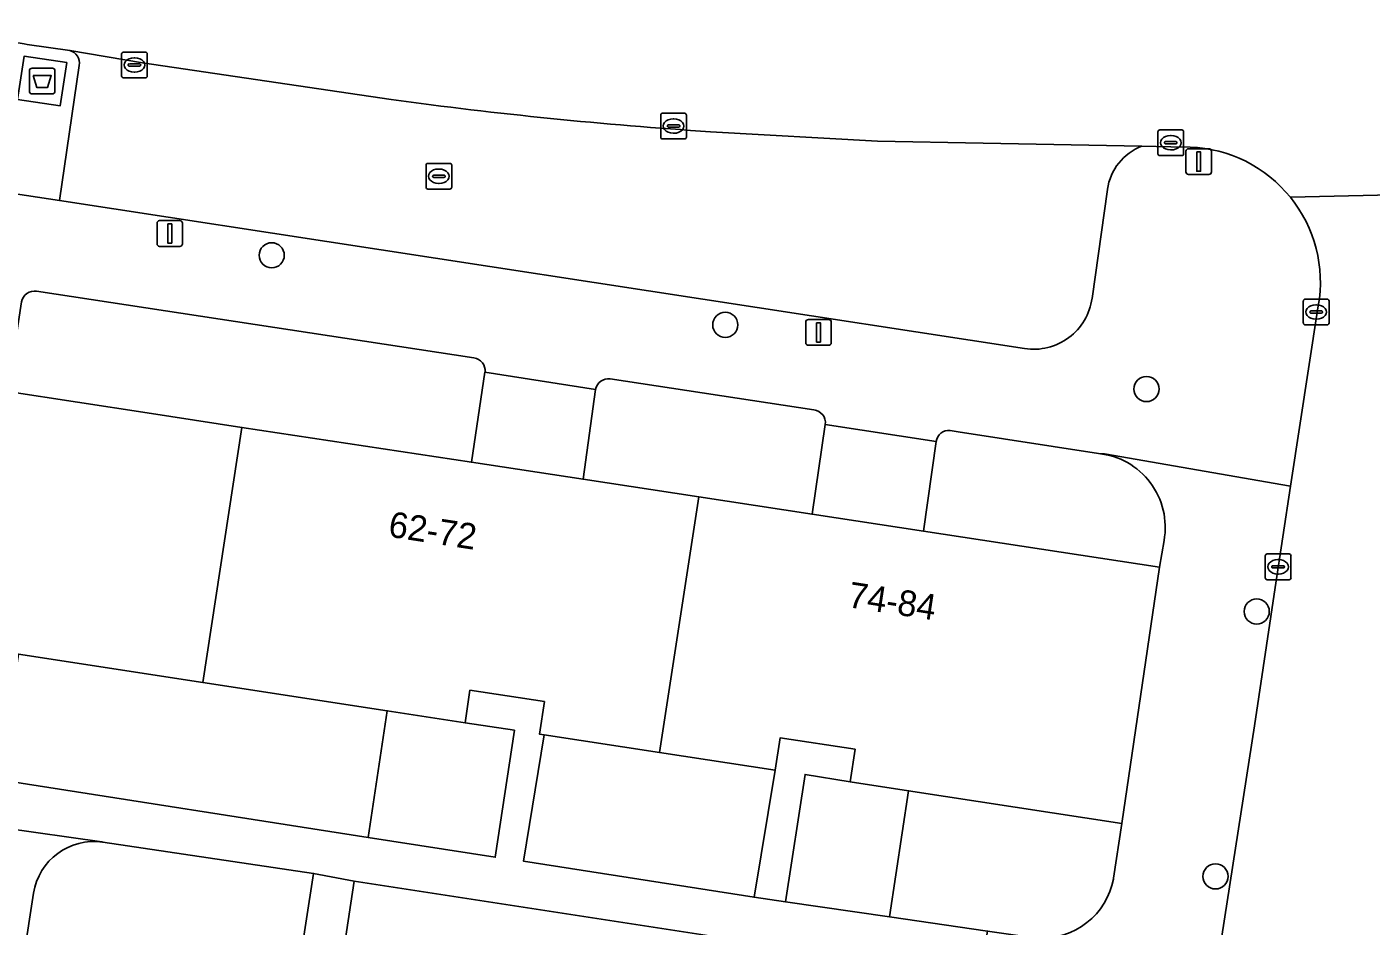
# Model space of a CAD drawing. Extents: x 161084 to 161928, y 385354 to 386522.
# Drawn here: x 161701.9 to 161754.2, y 385605.1 to 385640 of the extents above; entities that cross this region are included whole.
import ezdxf

# ---------------------------------------------------------------- set-up
doc = ezdxf.new("R2010")
doc.units = 0
for name, color, linetype in [('IMGEO_Afval_apart_plaats', 7, 'Continuous'), ('IMGEO_Boom', 7, 'Continuous'), ('IMGEO_Groenvoorziening', 7, 'Continuous'), ('IMGEO_Kolk', 7, 'Continuous'), ('IMGEO_Lichtmast', 7, 'Continuous'), ('IMGEO_Pand', 7, 'Continuous'), ('IMGEO_Pand_nummerreeks', 7, 'Continuous'), ('IMGEO_Parkeervlak_open', 7, 'Continuous'), ('IMGEO_Rijbaan_lokaal_open', 7, 'Continuous'), ('IMGEO_Rioolput', 7, 'Continuous'), ('IMGEO_Voetpad_gesloten', 7, 'Continuous'), ('IMGEO_Voetpad_open', 7, 'Continuous')]:
    doc.layers.add(name, color=color, linetype=linetype)

msp = doc.modelspace()

# ---------------------------------------------------------------- linework, layer by layer
at = {"layer": 'IMGEO_Afval_apart_plaats'}
for p, q in [((161702.13, 385638.394), (161702.92, 385638.394)), ((161702.92, 385638.394), (161702.13, 385638.394)), ((161702.03, 385637.494), (161702.03, 385638.294)), ((161702.03, 385638.294), (161702.03, 385637.494)), ((161703.02, 385638.294), (161703.02, 385637.494)), ((161703.02, 385637.494), (161703.02, 385638.294)), ((161702.92, 385637.394), (161702.13, 385637.394)), ((161702.13, 385637.394), (161702.92, 385637.394))]:
    msp.add_line(p, q, dxfattribs=at)
msp.add_lwpolyline([(161702.173, 385638.108), (161702.877, 385638.108), (161702.728, 385637.638), (161702.322, 385637.638), (161702.173, 385638.108)], dxfattribs=at)
for centre, start, end in [((161702.13, 385638.294), 90, 180), ((161702.13, 385638.294), 90, 180), ((161702.92, 385638.294), 0, 90), ((161702.92, 385638.294), 360, 90), ((161702.13, 385637.494), 180, 270), ((161702.13, 385637.494), 180, 270), ((161702.92, 385637.494), 270, 0), ((161702.92, 385637.494), 270, 0)]:
    msp.add_arc(centre, 0.1, start, end, dxfattribs=at)
at = {"layer": 'IMGEO_Boom'}
for centre in [(161711.448, 385631.125), (161729.079, 385628.421), (161745.453, 385625.929), (161749.736, 385617.286), (161748.133, 385606.997)]:
    msp.add_circle(centre, 0.489, dxfattribs=at)
at = {"layer": 'IMGEO_Groenvoorziening'}
for points in [[(161719.303, 385627.14), (161702.307, 385629.729)], [(161701.725, 385629.314), (161701.191, 385625.827), (161706.607, 385625.002), (161710.291, 385624.441), (161719.211, 385623.083), (161719.738, 385626.581)], [(161732.527, 385625.122), (161724.601, 385626.328)], [(161724.038, 385625.907), (161723.549, 385622.423), (161728.049, 385621.738), (161732.452, 385621.067), (161732.966, 385624.551)], [(161743.587, 385623.423), (161738.133, 385624.272), (161737.819, 385624.321)], [(161737.273, 385623.887), (161736.785, 385620.408), (161745.953, 385619.012), (161746.133, 385620.045)], [(161702.191, 385606.341), (161697.119, 385573.437), (161707.611, 385571.788), (161713.072, 385607.113), (161704.883, 385608.326)], [(161736.552, 385603.449), (161714.658, 385606.809), (161709.299, 385571.47), (161731.363, 385568.084)]]:
    msp.add_lwpolyline(points, dxfattribs=at)
for points in [[(161715.193, 385608.513), (161715.938, 385613.431), (161708.772, 385614.53), (161701.606, 385615.629), (161700.866, 385610.749), (161701.288, 385610.683)], [(161720.134, 385607.742), (161720.881, 385612.673), (161718.961, 385612.968), (161715.938, 385613.431), (161715.193, 385608.513)], [(161730.197, 385606.186), (161731.021, 385611.119), (161726.527, 385611.808), (161722.032, 385612.497), (161721.233, 385607.593)], [(161735.459, 385605.43), (161736.201, 385610.325), (161733.93, 385610.673), (161732.178, 385610.956), (161731.425, 385606.015)], [(161743.925, 385606.175), (161744.027, 385606.407), (161744.108, 385606.647), (161744.167, 385606.893), (161744.173, 385606.922), (161744.491, 385609.053), (161736.201, 385610.325), (161735.459, 385605.43), (161739.275, 385604.876), (161740.99, 385604.627), (161741.242, 385604.603), (161741.495, 385604.601), (161741.748, 385604.622), (161741.997, 385604.665), (161742.242, 385604.731), (161742.479, 385604.818), (161742.708, 385604.926), (161742.927, 385605.054), (161743.133, 385605.201), (161743.325, 385605.366), (161743.502, 385605.547), (161743.662, 385605.743), (161743.803, 385605.953)]]:
    msp.add_lwpolyline(points, close=True, dxfattribs=at)
for centre, radius, start, end in [((161702.221, 385629.234), 0.502, 80.1099, 170.8723), ((161719.236, 385626.639), 0.506, 353.4375, 82.3408), ((161724.54, 385625.822), 0.509, 83.1576, 170.4192), ((161732.459, 385624.615), 0.511, 352.7869, 82.3211), ((161737.777, 385623.813), 0.509, 85.2851, 171.6753), ((161743.305, 385620.562), 2.875, 349.6426, 84.368), ((161704.535, 385605.98), 2.372, 81.5728, 171.2351)]:
    msp.add_arc(centre, radius, start, end, dxfattribs=at)
at = {"layer": 'IMGEO_Kolk'}
for p, q in [((161705.611, 385638.091), (161705.611, 385638.943)), ((161705.686, 385639.017), (161706.538, 385639.017)), ((161706.612, 385638.943), (161706.612, 385638.091)), ((161705.87, 385638.511), (161705.87, 385638.523)), ((161706.308, 385638.474), (161705.91, 385638.474)), ((161705.913, 385638.56), (161706.311, 385638.56)), ((161706.099, 385638.797), (161706.124, 385638.797)), ((161706.354, 385638.523), (161706.354, 385638.511)), ((161706.538, 385638.017), (161705.686, 385638.017)), ((161706.122, 385638.237), (161706.097, 385638.237)), ((161726.569, 385635.719), (161726.569, 385636.571)), ((161726.644, 385636.645), (161727.496, 385636.645)), ((161727.057, 385636.425), (161727.082, 385636.425)), ((161727.57, 385636.571), (161727.57, 385635.719)), ((161726.828, 385636.139), (161726.828, 385636.151)), ((161727.266, 385636.102), (161726.868, 385636.102)), ((161726.871, 385636.188), (161727.269, 385636.188)), ((161727.08, 385635.865), (161727.055, 385635.865)), ((161727.312, 385636.151), (161727.312, 385636.139)), ((161745.894, 385635.071), (161745.894, 385635.923)), ((161745.969, 385635.997), (161746.821, 385635.997)), ((161746.382, 385635.777), (161746.407, 385635.777)), ((161746.895, 385635.923), (161746.895, 385635.071)), ((161727.496, 385635.645), (161726.644, 385635.645)), ((161746.153, 385635.491), (161746.153, 385635.503)), ((161746.591, 385635.454), (161746.193, 385635.454)), ((161746.196, 385635.54), (161746.594, 385635.54)), ((161746.405, 385635.217), (161746.38, 385635.217)), ((161746.637, 385635.503), (161746.637, 385635.491)), ((161746.821, 385634.997), (161745.969, 385634.997)), ((161751.548, 385628.496), (161751.548, 385629.348)), ((161751.623, 385629.422), (161752.475, 385629.422)), ((161751.807, 385628.916), (161751.807, 385628.928)), ((161751.85, 385628.965), (161752.248, 385628.965)), ((161752.036, 385629.202), (161752.061, 385629.202)), ((161752.291, 385628.928), (161752.291, 385628.916)), ((161752.549, 385629.348), (161752.549, 385628.496)), ((161752.475, 385628.422), (161751.623, 385628.422)), ((161752.245, 385628.879), (161751.847, 385628.879)), ((161752.059, 385628.642), (161752.034, 385628.642)), ((161750.143, 385619.523), (161750.995, 385619.523)), ((161750.068, 385618.597), (161750.068, 385619.449)), ((161750.327, 385619.017), (161750.327, 385619.029)), ((161750.37, 385619.066), (161750.768, 385619.066)), ((161750.556, 385619.303), (161750.581, 385619.303)), ((161750.811, 385619.029), (161750.811, 385619.017)), ((161751.069, 385619.449), (161751.069, 385618.597)), ((161750.995, 385618.523), (161750.143, 385618.523)), ((161750.765, 385618.98), (161750.367, 385618.98)), ((161750.579, 385618.743), (161750.554, 385618.743))]:
    msp.add_line(p, q, dxfattribs=at)
for points in [[(161705.611, 385638.091), (161705.611, 385638.943)], [(161705.686, 385639.017), (161706.538, 385639.017)], [(161706.612, 385638.943), (161706.612, 385638.091)], [(161706.538, 385638.017), (161705.686, 385638.017)], [(161726.569, 385635.719), (161726.569, 385636.571)], [(161726.644, 385636.645), (161727.496, 385636.645)], [(161727.57, 385636.571), (161727.57, 385635.719)], [(161745.894, 385635.071), (161745.894, 385635.923)], [(161745.969, 385635.997), (161746.821, 385635.997)], [(161746.895, 385635.923), (161746.895, 385635.071)], [(161727.496, 385635.645), (161726.644, 385635.645)], [(161746.821, 385634.997), (161745.969, 385634.997)], [(161751.548, 385628.496), (161751.548, 385629.348)], [(161751.623, 385629.422), (161752.475, 385629.422)], [(161752.549, 385629.348), (161752.549, 385628.496)], [(161752.475, 385628.422), (161751.623, 385628.422)], [(161750.143, 385619.523), (161750.995, 385619.523)], [(161750.068, 385618.597), (161750.068, 385619.449)], [(161751.069, 385619.449), (161751.069, 385618.597)], [(161750.995, 385618.523), (161750.143, 385618.523)]]:
    msp.add_lwpolyline(points, dxfattribs=at)
for centre, radius, start, end in [((161705.688, 385638.941), 0.0765, 91.552, 178.448), ((161705.688, 385638.941), 0.0765, 91.552, 178.448), ((161706.536, 385638.941), 0.0765, 1.552, 88.448), ((161706.536, 385638.941), 0.0765, 1.552, 88.448), ((161705.91, 385638.52), 0.0403, 85.8775, 175.7526), ((161705.907, 385638.51), 0.0366, 178.938, 274.7102), ((161706.311, 385638.517), 0.043, 264.8664, 352.4533), ((161706.315, 385638.522), 0.0386, 1.7309, 96.639), ((161705.688, 385638.093), 0.0765, 181.552, 268.448), ((161705.688, 385638.093), 0.0765, 181.552, 268.448), ((161706.536, 385638.093), 0.0765, 271.552, 358.448), ((161706.536, 385638.093), 0.0765, 271.552, 358.448), ((161726.646, 385636.569), 0.0765, 91.552, 178.448), ((161726.646, 385636.569), 0.0765, 91.552, 178.448), ((161727.494, 385636.569), 0.0765, 1.552, 88.448), ((161727.494, 385636.569), 0.0765, 1.552, 88.448), ((161726.646, 385635.721), 0.0765, 181.552, 268.448), ((161726.646, 385635.721), 0.0765, 181.552, 268.448), ((161726.868, 385636.148), 0.0403, 85.8775, 175.7526), ((161726.865, 385636.138), 0.0366, 178.938, 274.7102), ((161727.269, 385636.145), 0.043, 264.8664, 352.4533), ((161727.273, 385636.15), 0.0386, 1.7309, 96.639), ((161727.494, 385635.721), 0.0765, 271.552, 358.448), ((161727.494, 385635.721), 0.0765, 271.552, 358.448), ((161745.971, 385635.921), 0.0765, 91.552, 178.448), ((161745.971, 385635.921), 0.0765, 91.552, 178.448), ((161746.819, 385635.921), 0.0765, 1.552, 88.448), ((161746.819, 385635.921), 0.0765, 1.552, 88.448), ((161746.193, 385635.5), 0.0403, 85.8775, 175.7526), ((161746.19, 385635.49), 0.0366, 178.938, 274.7102), ((161746.594, 385635.497), 0.043, 264.8664, 352.4533), ((161746.598, 385635.502), 0.0386, 1.7309, 96.639), ((161745.971, 385635.073), 0.0765, 181.552, 268.448), ((161745.971, 385635.073), 0.0765, 181.552, 268.448), ((161746.819, 385635.073), 0.0765, 271.552, 358.448), ((161746.819, 385635.073), 0.0765, 271.552, 358.448), ((161751.625, 385629.346), 0.0765, 91.552, 178.448), ((161751.625, 385629.346), 0.0765, 91.552, 178.448), ((161751.847, 385628.925), 0.0403, 85.8775, 175.7526), ((161752.252, 385628.927), 0.0386, 1.7309, 96.639), ((161752.473, 385629.346), 0.0765, 1.552, 88.448), ((161752.473, 385629.346), 0.0765, 1.552, 88.448), ((161751.625, 385628.498), 0.0765, 181.552, 268.448), ((161751.625, 385628.498), 0.0765, 181.552, 268.448), ((161751.844, 385628.915), 0.0366, 178.938, 274.7102), ((161752.248, 385628.922), 0.043, 264.8664, 352.4533), ((161752.473, 385628.498), 0.0765, 271.552, 358.448), ((161752.473, 385628.498), 0.0765, 271.552, 358.448), ((161750.145, 385619.447), 0.0765, 91.552, 178.448), ((161750.145, 385619.447), 0.0765, 91.552, 178.448), ((161750.993, 385619.447), 0.0765, 1.552, 88.448), ((161750.993, 385619.447), 0.0765, 1.552, 88.448), ((161750.367, 385619.026), 0.0403, 85.8775, 175.7526), ((161750.364, 385619.016), 0.0366, 178.938, 274.7102), ((161750.768, 385619.023), 0.043, 264.8664, 352.4533), ((161750.772, 385619.028), 0.0386, 1.7309, 96.639), ((161750.145, 385618.599), 0.0765, 181.552, 268.448), ((161750.145, 385618.599), 0.0765, 181.552, 268.448), ((161750.993, 385618.599), 0.0765, 271.552, 358.448), ((161750.993, 385618.599), 0.0765, 271.552, 358.448)]:
    msp.add_arc(centre, radius, start, end, dxfattribs=at)
for centre, major_axis, ratio, start_param, end_param in [((161706.098, 385638.517), (-0.387, 0.002), 0.722429, 4.712389, 7.853982), ((161706.123, 385638.517), (-0.39, 0.002), 0.717154, 1.570796, 4.712389), ((161727.056, 385636.145), (-0.387, 0.002), 0.722429, 4.712389, 7.853982), ((161727.081, 385636.145), (-0.39, 0.002), 0.717154, 1.570796, 4.712389), ((161746.381, 385635.497), (-0.387, 0.002), 0.722429, 4.712389, 7.853982), ((161746.406, 385635.497), (-0.39, 0.002), 0.717154, 1.570796, 4.712389), ((161752.035, 385628.922), (-0.387, 0.002), 0.722429, 4.712389, 7.853982), ((161752.06, 385628.922), (-0.39, 0.002), 0.717154, 1.570796, 4.712389), ((161750.555, 385619.023), (-0.387, 0.002), 0.722429, 4.712389, 7.853982), ((161750.58, 385619.023), (-0.39, 0.002), 0.717154, 1.570796, 4.712389)]:
    msp.add_ellipse(centre, major_axis=major_axis, ratio=ratio, start_param=start_param, end_param=end_param, dxfattribs=at)
at = {"layer": 'IMGEO_Lichtmast'}
for p, q in [((161747.086, 385635.263), (161747.876, 385635.263)), ((161747.876, 385635.263), (161747.086, 385635.263)), ((161746.986, 385634.363), (161746.986, 385635.163)), ((161746.986, 385635.163), (161746.986, 385634.363)), ((161747.976, 385635.163), (161747.976, 385634.363)), ((161747.976, 385634.363), (161747.976, 385635.163)), ((161747.876, 385634.263), (161747.086, 385634.263)), ((161747.086, 385634.263), (161747.876, 385634.263)), ((161706.989, 385631.571), (161706.989, 385632.371)), ((161706.989, 385632.371), (161706.989, 385631.571)), ((161707.089, 385632.471), (161707.879, 385632.471)), ((161707.879, 385632.471), (161707.089, 385632.471)), ((161707.979, 385632.371), (161707.979, 385631.571)), ((161707.979, 385631.571), (161707.979, 385632.371)), ((161707.879, 385631.471), (161707.089, 385631.471)), ((161707.089, 385631.471), (161707.879, 385631.471)), ((161732.207, 385627.729), (161732.207, 385628.529)), ((161732.207, 385628.529), (161732.207, 385627.729)), ((161732.307, 385628.629), (161733.097, 385628.629)), ((161733.097, 385628.629), (161732.307, 385628.629)), ((161733.197, 385628.529), (161733.197, 385627.729)), ((161733.197, 385627.729), (161733.197, 385628.529)), ((161733.097, 385627.629), (161732.307, 385627.629)), ((161732.307, 385627.629), (161733.097, 385627.629))]:
    msp.add_line(p, q, dxfattribs=at)
for points in [[(161747.406, 385635.138), (161747.556, 385635.138), (161747.556, 385634.388), (161747.406, 385634.388), (161747.406, 385635.138)], [(161707.409, 385632.346), (161707.559, 385632.346), (161707.559, 385631.596), (161707.409, 385631.596), (161707.409, 385632.346)], [(161732.627, 385628.504), (161732.777, 385628.504), (161732.777, 385627.754), (161732.627, 385627.754), (161732.627, 385628.504)]]:
    msp.add_lwpolyline(points, dxfattribs=at)
for centre, start, end in [((161747.086, 385635.163), 90, 180), ((161747.086, 385635.163), 90, 180), ((161747.876, 385635.163), 0, 90), ((161747.876, 385635.163), 360, 90), ((161747.086, 385634.363), 180, 270), ((161747.086, 385634.363), 180, 270), ((161747.876, 385634.363), 270, 0), ((161747.876, 385634.363), 270, 0), ((161707.089, 385632.371), 90, 180), ((161707.089, 385632.371), 90, 180), ((161707.879, 385632.371), 0, 90), ((161707.879, 385632.371), 360, 90), ((161707.089, 385631.571), 180, 270), ((161707.089, 385631.571), 180, 270), ((161707.879, 385631.571), 270, 0), ((161707.879, 385631.571), 270, 0), ((161732.307, 385628.529), 90, 180), ((161732.307, 385628.529), 90, 180), ((161733.097, 385628.529), 0, 90), ((161733.097, 385628.529), 360, 90), ((161732.307, 385627.729), 180, 270), ((161732.307, 385627.729), 180, 270), ((161733.097, 385627.729), 270, 0), ((161733.097, 385627.729), 270, 0)]:
    msp.add_arc(centre, 0.1, start, end, dxfattribs=at)
at = {"layer": 'IMGEO_Pand'}
for points in [[(161706.607, 385625.002), (161701.191, 385625.827), (161696.834, 385626.49), (161692.212, 385627.194), (161691.504, 385622.944), (161691.308, 385621.667), (161690.64, 385617.31), (161695.295, 385616.596), (161695.489, 385617.86), (161698.408, 385617.412), (161698.214, 385616.149), (161701.606, 385615.629), (161708.772, 385614.53), (161710.291, 385624.441)], [(161723.549, 385622.423), (161719.211, 385623.083), (161710.291, 385624.441), (161708.772, 385614.53), (161715.938, 385613.431), (161718.961, 385612.968), (161719.155, 385614.231), (161722.045, 385613.788), (161721.851, 385612.525), (161722.032, 385612.497), (161726.527, 385611.808), (161728.049, 385621.738)], [(161728.049, 385621.738), (161726.527, 385611.808), (161731.021, 385611.119), (161731.215, 385612.382), (161734.124, 385611.936), (161733.93, 385610.673), (161736.201, 385610.325), (161744.491, 385609.053), (161745.953, 385619.012), (161736.785, 385620.408), (161732.452, 385621.067)]]:
    msp.add_lwpolyline(points, close=True, dxfattribs=at)
at = {"layer": 'IMGEO_Parkeervlak_open'}
for points in [[(161716.095, 385637.177), (161706.425, 385638.596), (161703.594, 385639.074)], [(161703.966, 385638.503), (161703.201, 385633.251), (161740.712, 385627.499)], [(161745.271, 385635.362), (161739.101, 385635.482), (161734.991, 385635.562), (161728.498, 385635.926)], [(161743.338, 385629.452), (161743.934, 385633.686)]]:
    msp.add_lwpolyline(points, dxfattribs=at)
for centre, radius, start, end in [((161703.489, 385638.599), 0.487, 348.6292, 77.5384), ((161739.697, 385809.071), 173.507, 262.18177, 266.29917), ((161746.026, 385633.389), 2.113, 110.9325, 171.9065), ((161741.06, 385629.773), 2.3, 261.2912, 351.9864)]:
    msp.add_arc(centre, radius, start, end, dxfattribs=at)
at = {"layer": 'IMGEO_Rijbaan_lokaal_open'}
for points in [[(161684.542, 385642.126), (161687.896, 385641.585), (161701.831, 385639.333), (161701.945, 385639.315), (161703.594, 385639.074), (161706.425, 385638.596), (161716.095, 385637.177)], [(161728.498, 385635.926), (161734.991, 385635.562), (161739.101, 385635.482), (161745.271, 385635.362), (161746.396, 385635.341), (161747.153, 385635.326)], [(161761.205, 385633.614), (161751.044, 385633.38)], [(161751.044, 385633.38), (161761.205, 385633.614)], [(161752.13, 385629.167), (161751.053, 385622.152), (161750.449, 385618.218), (161749.647, 385612.852), (161748.381, 385604.68)]]:
    msp.add_lwpolyline(points, dxfattribs=at)
for centre, radius, start, end in [((161739.697, 385809.071), 173.507, 262.18177, 266.29917), ((161746.962, 385630.081), 5.248, 38.9421, 87.9161), ((161746.96, 385630.081), 5.25, 349.9775, 38.9319)]:
    msp.add_arc(centre, radius, start, end, dxfattribs=at)
at = {"layer": 'IMGEO_Rioolput'}
for p, q in [((161717.52, 385634.695), (161718.372, 385634.695)), ((161717.445, 385633.769), (161717.445, 385634.621)), ((161717.704, 385634.189), (161717.704, 385634.201)), ((161718.142, 385634.152), (161717.744, 385634.152)), ((161717.747, 385634.238), (161718.145, 385634.238)), ((161717.933, 385634.475), (161717.958, 385634.475)), ((161718.188, 385634.201), (161718.188, 385634.189)), ((161718.446, 385634.621), (161718.446, 385633.769)), ((161718.372, 385633.695), (161717.52, 385633.695)), ((161717.956, 385633.915), (161717.931, 385633.915))]:
    msp.add_line(p, q, dxfattribs=at)
for points in [[(161717.52, 385634.695), (161718.372, 385634.695)], [(161717.445, 385633.769), (161717.445, 385634.621)], [(161718.446, 385634.621), (161718.446, 385633.769)], [(161718.372, 385633.695), (161717.52, 385633.695)]]:
    msp.add_lwpolyline(points, dxfattribs=at)
for centre, radius, start, end in [((161717.522, 385634.619), 0.0765, 91.552, 178.448), ((161717.522, 385634.619), 0.0765, 91.552, 178.448), ((161718.37, 385634.619), 0.0765, 1.552, 88.448), ((161718.37, 385634.619), 0.0765, 1.552, 88.448), ((161717.744, 385634.198), 0.0403, 85.8775, 175.7526), ((161717.741, 385634.188), 0.0366, 178.938, 274.7102), ((161718.145, 385634.195), 0.043, 264.8664, 352.4533), ((161718.149, 385634.2), 0.0386, 1.7309, 96.639), ((161717.522, 385633.771), 0.0765, 181.552, 268.448), ((161717.522, 385633.771), 0.0765, 181.552, 268.448), ((161718.37, 385633.771), 0.0765, 271.552, 358.448), ((161718.37, 385633.771), 0.0765, 271.552, 358.448)]:
    msp.add_arc(centre, radius, start, end, dxfattribs=at)
for centre, major_axis, ratio, start_param, end_param in [((161717.932, 385634.195), (-0.387, 0.002), 0.722429, 4.712389, 7.853982), ((161717.957, 385634.195), (-0.39, 0.002), 0.717154, 1.570796, 4.712389)]:
    msp.add_ellipse(centre, major_axis=major_axis, ratio=ratio, start_param=start_param, end_param=end_param, dxfattribs=at)
at = {"layer": 'IMGEO_Voetpad_gesloten'}
msp.add_lwpolyline([(161703.481, 385638.609), (161701.821, 385638.859), (161701.568, 385637.18), (161703.228, 385636.93)], close=True, dxfattribs=at)
at = {"layer": 'IMGEO_Voetpad_open'}
for points in [[(161701.328, 385638.883), (161700.616, 385633.647), (161703.201, 385633.251), (161703.966, 385638.503)], [(161703.594, 385639.074), (161701.945, 385639.315), (161701.831, 385639.333)], [(161747.153, 385635.326), (161746.396, 385635.341), (161745.271, 385635.362)], [(161703.201, 385633.251), (161700.616, 385633.647), (161691.142, 385635.1)], [(161743.934, 385633.686), (161743.338, 385629.452)], [(161740.712, 385627.499), (161703.201, 385633.251)], [(161702.307, 385629.729), (161719.303, 385627.14)], [(161737.819, 385624.321), (161738.133, 385624.272), (161743.587, 385623.423), (161743.814, 385623.414), (161751.053, 385622.152), (161752.13, 385629.167)], [(161719.738, 385626.581), (161724.038, 385625.907)], [(161724.601, 385626.328), (161732.527, 385625.122)], [(161732.966, 385624.551), (161737.273, 385623.887)], [(161749.647, 385612.852), (161750.449, 385618.218), (161751.053, 385622.152), (161743.814, 385623.414), (161743.587, 385623.423)], [(161746.133, 385620.045), (161745.953, 385619.012), (161744.491, 385609.053), (161744.173, 385606.922), (161744.167, 385606.893), (161744.108, 385606.647), (161744.027, 385606.407), (161743.925, 385606.175), (161743.803, 385605.953), (161743.662, 385605.743), (161743.502, 385605.547), (161743.325, 385605.366), (161743.133, 385605.201), (161742.927, 385605.054)], [(161721.233, 385607.593), (161722.032, 385612.497), (161721.851, 385612.525), (161722.045, 385613.788), (161719.155, 385614.231), (161718.961, 385612.968), (161720.881, 385612.673), (161720.134, 385607.742), (161715.193, 385608.513), (161701.288, 385610.683), (161700.995, 385608.885), (161704.848, 385608.336), (161704.883, 385608.326), (161713.072, 385607.113), (161714.658, 385606.809), (161736.552, 385603.449)], [(161736.312, 385565.923), (161736.551, 385567.468), (161741.992, 385602.681), (161744.77, 385602.246), (161745.054, 385602.214), (161745.341, 385602.208), (161745.626, 385602.228), (161745.909, 385602.273), (161746.186, 385602.343), (161746.456, 385602.438), (161746.717, 385602.556), (161746.966, 385602.697), (161747.201, 385602.86), (161747.421, 385603.043), (161747.624, 385603.245), (161747.807, 385603.465), (161747.971, 385603.7), (161748.113, 385603.948), (161748.232, 385604.209), (161748.327, 385604.479), (161748.381, 385604.68), (161749.647, 385612.852)], [(161704.883, 385608.326), (161704.848, 385608.336), (161700.995, 385608.885), (161700.619, 385606.575), (161698.975, 385595.889), (161698.823, 385594.901), (161695.859, 385575.628), (161695.631, 385574.145), (161695.311, 385572.063), (161693.826, 385562.411), (161693.582, 385560.823), (161696.695, 385560.34), (161705.534, 385558.969), (161707.374, 385558.705), (161707.433, 385559.106), (161707.615, 385560.292), (161709.056, 385569.786)], [(161738.568, 385600.711), (161739.275, 385604.876), (161735.459, 385605.43), (161731.425, 385606.015), (161730.197, 385606.186), (161721.233, 385607.593)], [(161709.056, 385569.786), (161709.299, 385571.47), (161714.658, 385606.809), (161713.072, 385607.113), (161707.611, 385571.788), (161697.119, 385573.437), (161702.191, 385606.341)]]:
    msp.add_lwpolyline(points, dxfattribs=at)
for points in [[(161701.568, 385637.18), (161701.821, 385638.859), (161703.481, 385638.609), (161703.228, 385636.93)], [(161719.738, 385626.581), (161719.211, 385623.083), (161723.549, 385622.423), (161724.038, 385625.907)], [(161736.785, 385620.408), (161737.273, 385623.887), (161732.966, 385624.551), (161732.452, 385621.067)], [(161731.425, 385606.015), (161732.178, 385610.956), (161733.93, 385610.673), (161734.124, 385611.936), (161731.215, 385612.382), (161731.021, 385611.119), (161730.197, 385606.186)]]:
    msp.add_lwpolyline(points, close=True, dxfattribs=at)
for centre, radius, start, end in [((161703.489, 385638.599), 0.487, 348.6292, 77.5384), ((161746.026, 385633.389), 2.113, 110.9325, 171.9065), ((161746.962, 385630.081), 5.248, 38.9421, 87.9161), ((161746.96, 385630.081), 5.25, 349.9775, 38.9319), ((161702.221, 385629.234), 0.502, 80.1099, 170.8723), ((161741.06, 385629.773), 2.3, 261.2912, 351.9864), ((161719.236, 385626.639), 0.506, 353.4375, 82.3408), ((161724.54, 385625.822), 0.509, 83.1576, 170.4192), ((161732.459, 385624.615), 0.511, 352.7869, 82.3211), ((161737.777, 385623.813), 0.509, 85.2851, 171.6753), ((161743.305, 385620.562), 2.875, 349.6426, 84.368), ((161704.535, 385605.98), 2.372, 81.5728, 171.2351)]:
    msp.add_arc(centre, radius, start, end, dxfattribs=at)

# ---------------------------------------------------------------- texts
at = {"layer": 'IMGEO_Pand_nummerreeks'}
for s, rotation, p in [('62-72', 351.2817, (161715.943, 385620.2)), ('74-84', 351.2832, (161733.809, 385617.46))]:
    msp.add_text(s, height=1, rotation=rotation, dxfattribs=at).set_placement(p)

doc.saveas('drawing.dxf')
